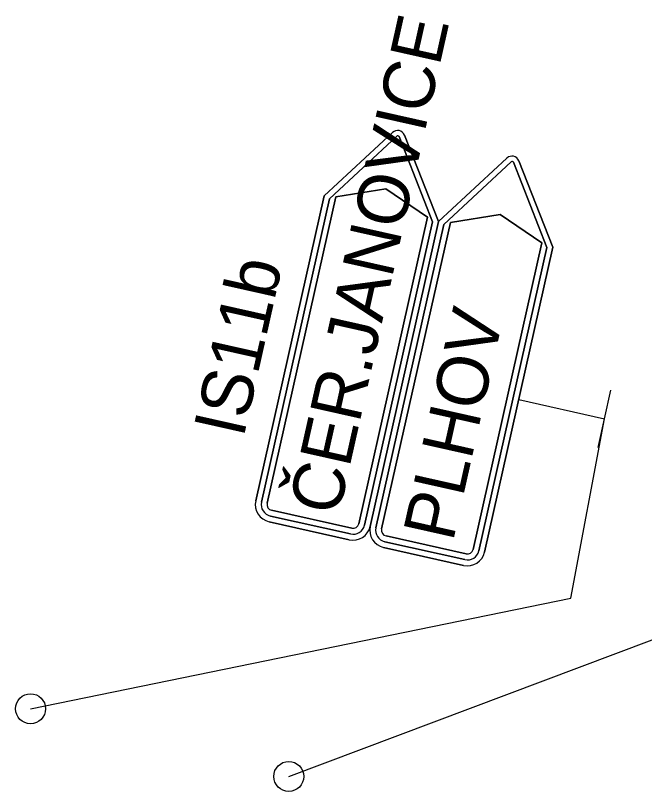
# Model space of a CAD drawing. Extents: x -688893 to -679983, y -1088371 to -1075771.
# Drawn here: x -684109 to -683465, y -1080198 to -1079404 of the extents above; entities that cross this region are included whole.
import ezdxf

# ---------------------------------------------------------------- set-up
doc = ezdxf.new("R2010")
doc.units = 0
for name, color, linetype in [('SDZ', 7, 'Continuous'), ('SDZ ozn', 7, 'Continuous'), ('SDZ plochy', 7, 'Continuous'), ('SDZ symbol', 7, 'Continuous')]:
    doc.layers.add(name, color=color, linetype=linetype)

msp = doc.modelspace()

# ---------------------------------------------------------------- linework, layer by layer
at = {"layer": 'SDZ'}
for p, q in [((-683792.64, -1079588.33), (-683722.6, -1079523.31)), ((-683722.75, -1079523.45), (-683722.75, -1079523.45)), ((-683718.38, -1079527.11), (-683787.18, -1079591.4)), ((-683681.8, -1079615.03), (-683715.96, -1079527.66)), ((-683710.52, -1079526.05), (-683675.55, -1079614.59)), ((-683675.55, -1079614.59), (-683605.5, -1079549.57)), ((-683601.29, -1079553.37), (-683670.09, -1079617.66)), ((-683605.66, -1079549.71), (-683605.66, -1079549.71)), ((-683564.7, -1079641.29), (-683598.87, -1079553.92)), ((-683593.43, -1079552.31), (-683558.46, -1079640.85)), ((-683780.54, -1079589.2), (-683729.5, -1079580.97)), ((-683729.5, -1079580.97), (-683686.86, -1079610.21)), ((-683862.62, -1079900.38), (-683792.64, -1079588.33)), ((-683787.18, -1079591.4), (-683856.77, -1079901.69)), ((-683850.91, -1079903.01), (-683780.54, -1079589.2)), ((-683686.86, -1079610.21), (-683757.24, -1079924.01)), ((-683663.44, -1079615.46), (-683612.41, -1079607.23)), ((-683612.41, -1079607.23), (-683569.77, -1079636.47)), ((-683751.38, -1079925.33), (-683681.8, -1079615.03)), ((-683745.53, -1079926.64), (-683675.55, -1079614.59)), ((-683675.55, -1079614.59), (-683745.53, -1079926.64)), ((-683670.09, -1079617.66), (-683739.67, -1079927.95)), ((-683733.82, -1079929.26), (-683663.44, -1079615.46)), ((-683569.77, -1079636.47), (-683640.15, -1079950.27)), ((-683634.29, -1079951.58), (-683564.7, -1079641.29)), ((-683558.46, -1079640.85), (-683628.44, -1079952.9)), ((-683512.19, -1079845.84), (-683499.06, -1079787.29)), ((-683593.45, -1079796.87), (-683505.63, -1079816.57)), ((-683764.4, -1079928.55), (-683846.37, -1079910.17)), ((-683847.68, -1079916.03), (-683765.72, -1079934.41)), ((-683767.03, -1079940.26), (-683848.99, -1079921.88)), ((-683647.31, -1079954.81), (-683729.28, -1079936.43)), ((-683730.59, -1079942.29), (-683648.63, -1079960.67)), ((-683649.94, -1079966.52), (-683731.9, -1079948.14))]:
    msp.add_line(p, q, dxfattribs=at)
for points in [[(-683828.78, -1080182.62), (-682861.97, -1079818.86), (-682826.16, -1079627.87)], [(-684093.15, -1080113.32), (-683540.05, -1080000), (-683505.63, -1079816.57)]]:
    msp.add_lwpolyline(points, dxfattribs=at)
for centre in [(-684093.15, -1080113.32), (-683828.78, -1080182.62)]:
    msp.add_circle(centre, 15.36, dxfattribs=at)
for centre, radius, start, end in [((-683717.49, -1079528.81), 7.5, 21.5518, 132.87007), ((-683717.36, -1079528.21), 1.5, 21.35649, 133.05937), ((-683600.4, -1079555.06), 7.5, 21.5518, 132.87007), ((-683600.27, -1079554.47), 1.5, 21.35649, 133.05937), ((-683845.06, -1079904.32), 18, 167.36003, 257.36003), ((-683845.06, -1079904.32), 12, 167.36003, 257.36003), ((-683845.06, -1079904.32), 6, 167.36003, 257.36003), ((-683763.09, -1079922.7), 18, 257.36003, 347.36003), ((-683763.09, -1079922.7), 12, 257.36003, 347.36003), ((-683763.09, -1079922.7), 6, 257.36003, 347.36003), ((-683727.96, -1079930.58), 18, 167.36003, 257.36003), ((-683727.96, -1079930.58), 12, 167.36003, 257.36003), ((-683727.96, -1079930.58), 6, 167.36003, 257.36003), ((-683646, -1079948.96), 18, 257.36003, 347.36003), ((-683646, -1079948.96), 12, 257.36003, 347.36003), ((-683646, -1079948.96), 6, 257.36003, 347.36003)]:
    msp.add_arc(centre, radius, start, end, dxfattribs=at)
at = {"layer": 'SDZ plochy'}
for p, q in [((-683722.6, -1079523.31), (-683792.64, -1079588.33)), ((-683787.18, -1079591.4), (-683718.38, -1079527.11)), ((-683718.38, -1079527.11), (-683787.18, -1079591.4)), ((-683715.96, -1079527.66), (-683681.8, -1079615.03)), ((-683681.8, -1079615.03), (-683715.96, -1079527.66)), ((-683675.55, -1079614.59), (-683710.52, -1079526.05)), ((-683605.5, -1079549.57), (-683675.55, -1079614.59)), ((-683670.09, -1079617.66), (-683601.29, -1079553.37)), ((-683601.29, -1079553.37), (-683670.09, -1079617.66)), ((-683598.87, -1079553.92), (-683564.7, -1079641.29)), ((-683564.7, -1079641.29), (-683598.87, -1079553.92)), ((-683558.46, -1079640.85), (-683593.43, -1079552.31)), ((-683729.5, -1079580.97), (-683780.54, -1079589.2)), ((-683780.54, -1079589.2), (-683729.5, -1079580.97)), ((-683686.86, -1079610.21), (-683729.5, -1079580.97)), ((-683729.5, -1079580.97), (-683686.86, -1079610.21)), ((-683792.64, -1079588.33), (-683862.62, -1079900.38)), ((-683856.77, -1079901.69), (-683787.18, -1079591.4)), ((-683787.18, -1079591.4), (-683856.77, -1079901.69)), ((-683780.54, -1079589.2), (-683850.91, -1079903.01)), ((-683850.91, -1079903.01), (-683780.54, -1079589.2)), ((-683757.24, -1079924.01), (-683686.86, -1079610.21)), ((-683686.86, -1079610.21), (-683757.24, -1079924.01)), ((-683612.41, -1079607.23), (-683663.44, -1079615.46)), ((-683663.44, -1079615.46), (-683612.41, -1079607.23)), ((-683569.77, -1079636.47), (-683612.41, -1079607.23)), ((-683612.41, -1079607.23), (-683569.77, -1079636.47)), ((-683681.8, -1079615.03), (-683751.38, -1079925.33)), ((-683751.38, -1079925.33), (-683681.8, -1079615.03)), ((-683675.55, -1079614.59), (-683745.53, -1079926.64)), ((-683745.53, -1079926.64), (-683675.55, -1079614.59)), ((-683739.67, -1079927.95), (-683670.09, -1079617.66)), ((-683670.09, -1079617.66), (-683739.67, -1079927.95)), ((-683663.44, -1079615.46), (-683733.82, -1079929.26)), ((-683733.82, -1079929.26), (-683663.44, -1079615.46)), ((-683640.15, -1079950.27), (-683569.77, -1079636.47)), ((-683569.77, -1079636.47), (-683640.15, -1079950.27)), ((-683564.7, -1079641.29), (-683634.29, -1079951.58)), ((-683634.29, -1079951.58), (-683564.7, -1079641.29)), ((-683628.44, -1079952.9), (-683558.46, -1079640.85)), ((-683846.37, -1079910.17), (-683764.4, -1079928.55)), ((-683764.4, -1079928.55), (-683846.37, -1079910.17)), ((-683765.72, -1079934.41), (-683847.68, -1079916.03)), ((-683847.68, -1079916.03), (-683765.72, -1079934.41)), ((-683848.99, -1079921.88), (-683767.03, -1079940.26)), ((-683729.28, -1079936.43), (-683647.31, -1079954.81)), ((-683647.31, -1079954.81), (-683729.28, -1079936.43)), ((-683648.63, -1079960.67), (-683730.59, -1079942.29)), ((-683730.59, -1079942.29), (-683648.63, -1079960.67)), ((-683731.9, -1079948.14), (-683649.94, -1079966.52))]:
    msp.add_line(p, q, dxfattribs=at)
for centre, radius, start, end in [((-683717.49, -1079528.81), 7.5, 21.5518, 132.87007), ((-683717.36, -1079528.21), 1.5, 21.35649, 133.05937), ((-683717.36, -1079528.21), 1.5, 21.35649, 133.05937), ((-683600.4, -1079555.06), 7.5, 21.5518, 132.87007), ((-683600.27, -1079554.47), 1.5, 21.35649, 133.05937), ((-683600.27, -1079554.47), 1.5, 21.35649, 133.05937), ((-683845.06, -1079904.32), 18, 167.36003, 257.36003), ((-683845.06, -1079904.32), 12, 167.36003, 257.36003), ((-683845.06, -1079904.32), 12, 167.36003, 257.36003), ((-683845.06, -1079904.32), 6, 167.36003, 257.36003), ((-683845.06, -1079904.32), 6, 167.36003, 257.36003), ((-683763.09, -1079922.7), 18, 257.36003, 347.36003), ((-683763.09, -1079922.7), 12, 257.36003, 347.36003), ((-683763.09, -1079922.7), 12, 257.36003, 347.36003), ((-683763.09, -1079922.7), 6, 257.36003, 347.36003), ((-683763.09, -1079922.7), 6, 257.36003, 347.36003), ((-683727.96, -1079930.58), 18, 167.36003, 257.36003), ((-683727.96, -1079930.58), 12, 167.36003, 257.36003), ((-683727.96, -1079930.58), 12, 167.36003, 257.36003), ((-683727.96, -1079930.58), 6, 167.36003, 257.36003), ((-683727.96, -1079930.58), 6, 167.36003, 257.36003), ((-683646, -1079948.96), 18, 257.36003, 347.36003), ((-683646, -1079948.96), 12, 257.36003, 347.36003), ((-683646, -1079948.96), 12, 257.36003, 347.36003), ((-683646, -1079948.96), 6, 257.36003, 347.36003), ((-683646, -1079948.96), 6, 257.36003, 347.36003)]:
    msp.add_arc(centre, radius, start, end, dxfattribs=at)

# ---------------------------------------------------------------- texts
at = {"layer": 'SDZ ozn'}
msp.add_text('IS11b', height=52.5, rotation=77.36003, dxfattribs=at).set_placement((-683875.27, -1079837.11))
at = {"layer": 'SDZ symbol'}
for s, p in [('ČER.JANOVICE', (-683777.97, -1079917.09)), ('PLHOV', (-683660.88, -1079943.35))]:
    msp.add_text(s, height=52.5, rotation=77.36003, dxfattribs=at).set_placement(p)

doc.saveas('drawing.dxf')
